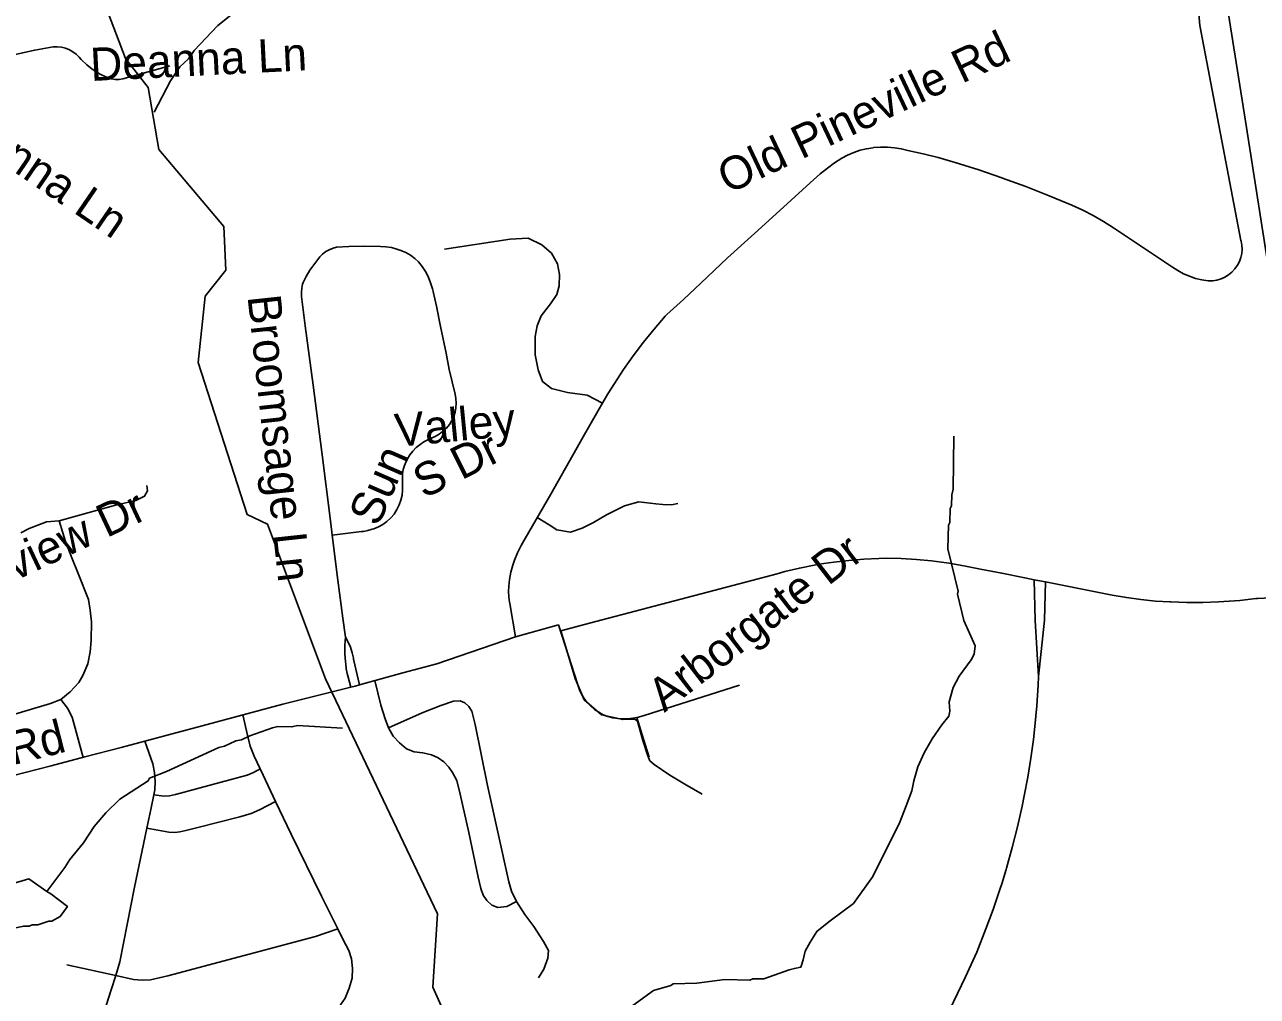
# Model space of a CAD drawing. Extents: x 1383679 to 1536984, y 460658 to 651027.
# Drawn here: x 1435276 to 1438807, y 509221 to 512005 of the extents above; entities that cross this region are included whole.
import ezdxf

# ---------------------------------------------------------------- set-up
doc = ezdxf.new("R2010")
doc.units = 0
for name, color, linetype in [('Exist Hydrographic Creek Single Shore', 7, 'Continuous'), ('Exist Hydrographic Misc Water Feature', 7, 'Continuous'), ('Exist Railroad Mainline', 7, 'Continuous'), ('Exist Road Non-System Type 51', 7, 'Continuous'), ('Exist Road Non-System Type 51 Label', 7, 'Continuous')]:
    doc.layers.add(name, color=color, linetype=linetype)

msp = doc.modelspace()

# ---------------------------------------------------------------- linework, layer by layer
at = {"layer": 'Exist Hydrographic Creek Single Shore'}
msp.add_lwpolyline([(1436493.4, 509139), (1436445.4, 509248.2), (1436458.4, 509458.1), (1436137.4, 510130.8), (1435971.4, 510574), (1435913.4, 510601.5), (1435772.4, 511037.6), (1435792.4, 511227.6), (1435852.4, 511301.8), (1435846.4, 511426.7), (1435659.5, 511647.1), (1435629.4, 511825), (1435564.4, 511908.3), (1435405.4, 512328.4), (1435437.4, 512695.4), (1435492.5, 512937.2), (1435523.4, 513268), (1435362.5, 513937.6), (1435309.4, 514240.7), (1435323.4, 514539.1), (1435285.5, 514707.3), (1435189.5, 514925.8)], dxfattribs=at)
at = {"layer": 'Exist Hydrographic Misc Water Feature'}
for points in [[(1435646.5, 511754.1), (1435693.3, 511844.4), (1435720.1, 511883.8), (1435744.6, 511907.2), (1435761.2, 511930.8), (1435828.7, 512003.1), (1435885.7, 512048)], [(1437924.4, 510065.2), (1437936, 510106.7), (1437952.8, 510138.4), (1437987.8, 510185.5), (1437996.1, 510201.4), (1437998.7, 510225.3), (1437966.3, 510298), (1437948.8, 510373.6), (1437950.1, 510382.3), (1437921, 510503.2), (1437922.1, 510570.9), (1437926.3, 510578.8), (1437927.2, 510618.7), (1437931.3, 510626.6), (1437932, 510658.6), (1437936.3, 510674.5), (1437937.7, 510826.4)], [(1437466.5, 509297.7), (1437481.1, 509301.4), (1437499.3, 509304.6), (1437505.7, 509325.9), (1437512.2, 509350.9), (1437525.8, 509376.9), (1437545.6, 509407.5), (1437579.7, 509435.4), (1437620.9, 509465.5), (1437650, 509487.6), (1437705.4, 509565.2), (1437743.9, 509642), (1437781.3, 509715.2), (1437801.4, 509767.3), (1437817.8, 509810), (1437823.3, 509838.5), (1437834.8, 509878.9), (1437852.4, 509919.1), (1437875.9, 509959.1), (1437903, 509999.2), (1437923.8, 510023.8), (1437926.2, 510038.9), (1437924.4, 510065.2)], [(1436185.8, 509989.7), (1436057.4, 509997), (1436041.3, 509993.4), (1436001.3, 509994.3), (1435985.2, 509990.7), (1435920.7, 509968.1), (1435896.4, 509956.7), (1435880.3, 509953), (1435848, 509937.8), (1435831.9, 509934.1), (1435682.4, 509865.5), (1435633.7, 509846.8), (1435629.8, 509838.7), (1435548.6, 509786.5), (1435507.8, 509747.5), (1435474.9, 509708.3), (1435443.8, 509661), (1435404.9, 509613.9), (1435390.3, 509590.2), (1435338.6, 509521.7)], [(1435338.6, 509521.7), (1435350.7, 509515.1), (1435398, 509479.1), (1435377.3, 509450.6), (1435353, 509437.1), (1435345, 509437.3), (1435312.8, 509426), (1435296.8, 509426.4), (1435288.7, 509422.6), (1435272.7, 509422.9), (1435240.5, 509415.7), (1435200.1, 509396.6), (1435184.1, 509396.9), (1435170.2, 509403.3), (1435159, 509437.5), (1435157.9, 509477.5), (1435162.2, 509493.4), (1435174.5, 509509.1), (1435233.2, 509541.8), (1435287.6, 509558.5), (1435338.6, 509521.7)], [(1436839.9, 508986.1), (1436882.6, 509030.9), (1436973.1, 509148.8), (1437005.8, 509180.1), (1437008, 509188), (1437077.1, 509238.4), (1437126.5, 509252.5), (1437133.5, 509257.2), (1437201.5, 509259.6), (1437281.8, 509269.8), (1437353.8, 509268.2), (1437361.9, 509272), (1437393.9, 509271.3), (1437466.5, 509297.7)]]:
    msp.add_lwpolyline(points, dxfattribs=at)
at = {"layer": 'Exist Railroad Mainline'}
msp.add_lwpolyline([(1438885.5, 511015.1), (1438773.4, 511728.4), (1438664.9, 512414.7)], dxfattribs=at)
at = {"layer": 'Exist Road Non-System Type 51'}
for p, q in [((1438168.1, 510415), (1438200.4, 510408.6)), ((1435396.2, 509311.8), (1435536.4, 509281.3))]:
    msp.add_line(p, q, dxfattribs=at)
for points in [[(1436681.7, 510251.1), (1436665.5, 510346.4), (1436664.7, 510350.4), (1436662.5, 510365.7), (1436661.8, 510380.9), (1436662.5, 510396.2), (1436664.9, 510415.6), (1436669, 510436.5), (1436674.5, 510457), (1436679.4, 510471.3), (1436687.9, 510492.3), (1436697.8, 510512.6), (1436709.3, 510532.7), (1436782.7, 510660.3), (1436845.8, 510771.6), (1436875.8, 510824), (1436918.2, 510897.8), (1436946.7, 510947.2), (1436965.3, 510977.3), (1436991.4, 511017.2), (1437019, 511056.3), (1437019.2, 511056.6), (1437048.5, 511095.4), (1437079, 511133.1), (1437110.8, 511170.1), (1437115.9, 511174.6), (1437163.3, 511217.9), (1437212.5, 511264.2), (1437289.5, 511337.1), (1437366.3, 511406.5), (1437449.7, 511481.9), (1437526, 511551.5), (1437554.8, 511577.6), (1437575.8, 511594.3), (1437596.1, 511609.7), (1437617.4, 511622.9), (1437633.5, 511631.4), (1437651, 511639), (1437669.1, 511645.1), (1437687.6, 511649.6), (1437706.4, 511652.7), (1437707.7, 511652.8), (1437727.6, 511654.3), (1437747.5, 511654.3), (1437767.4, 511652.7), (1437787.1, 511649.5), (1437806.5, 511644.8), (1437849.8, 511635.5), (1437892.6, 511624.7), (1437935.1, 511612.4), (1437941.2, 511610.5), (1438009.4, 511588.9), (1438075, 511566.4), (1438077, 511565.8), (1438144.2, 511541.2), (1438210.8, 511515.1), (1438276.2, 511487.8), (1438307.2, 511473.7), (1438337.5, 511458.2), (1438367.1, 511441.3), (1438395.8, 511423.1), (1438423.7, 511403.6), (1438564.7, 511310.5), (1438580.1, 511300.4), (1438596.3, 511291.6), (1438613.2, 511284.2), (1438630.7, 511278.2), (1438648.6, 511273.8), (1438666.8, 511271), (1438667.5, 511270.9), (1438679.7, 511271.4), (1438691.7, 511273.4), (1438703.4, 511277), (1438714.5, 511282.1), (1438724.9, 511288.6), (1438734.3, 511296.3), (1438742.7, 511305.2), (1438749.9, 511315.1), (1438750.3, 511315.8), (1438755.9, 511326.4), (1438760, 511337.6), (1438762.6, 511349.2), (1438763.6, 511361.1), (1438763.1, 511373), (1438760.9, 511384.7), (1438760.5, 511386.4), (1438643, 512002.4), (1438638.6, 512047.5)], [(1435691.9, 511886.9), (1435556.9, 511850.1), (1435546.2, 511848.4), (1435535.3, 511848.3), (1435524.5, 511849.7), (1435514.1, 511852.7), (1435509.7, 511854.4), (1435493.7, 511862), (1435478.4, 511871), (1435464, 511881.3), (1435453.7, 511889.9), (1435437.2, 511905.6), (1435432.1, 511911.8), (1435423.5, 511920.1), (1435414, 511927.2), (1435403.6, 511933), (1435392.5, 511937.3), (1435380.9, 511940.2), (1435369.1, 511941.5), (1435357.2, 511941.2), (1435304.2, 511932.4), (1435247.9, 511919.5)], [(1436156.9, 510542.2), (1436152.6, 510576.3), (1436127.3, 510780.6), (1436101.8, 510972.3), (1436079.3, 511142.4), (1436068.7, 511226.8), (1436068.3, 511238.6), (1436069.3, 511250.1), (1436071.8, 511261.7), (1436073.1, 511266), (1436082.2, 511283.8), (1436092.9, 511301.6), (1436098.5, 511309.8), (1436121.1, 511339.8), (1436129.2, 511348), (1436138.3, 511354.9), (1436148.3, 511360.5), (1436159, 511364.7), (1436169.2, 511367.3), (1436204.4, 511369.2), (1436249.4, 511370.3), (1436295.5, 511369.8), (1436310.8, 511368.9), (1436326.3, 511366.4), (1436338.9, 511363), (1436353.2, 511358.4), (1436367.4, 511352.2), (1436380.7, 511344.4), (1436393.1, 511335.3), (1436403.9, 511325.3), (1436414.7, 511311.9), (1436423.9, 511297.7), (1436431.3, 511283.2), (1436438.6, 511265.8), (1436444.4, 511247.9), (1436446.4, 511240.4), (1436455.3, 511198.7), (1436467, 511140.2), (1436483.1, 511063.9), (1436492.1, 511017.5), (1436508.7, 510946.7), (1436511.1, 510933.9), (1436511.9, 510920.8), (1436511.2, 510907.8), (1436508.8, 510895), (1436505, 510882.5), (1436504.9, 510882.1), (1436499.8, 510870.8), (1436492.8, 510859.6), (1436484.4, 510849.5), (1436475, 510840.8), (1436473, 510839.3), (1436463, 510831.7), (1436451.6, 510825.4), (1436444.8, 510822.5), (1436419.7, 510809.6), (1436408.3, 510802.1), (1436397.7, 510793.3), (1436388.1, 510783.5), (1436379.6, 510772.7), (1436372.1, 510760.9), (1436371.2, 510759.2), (1436365.8, 510747.3), (1436363.9, 510742.1), (1436360.4, 510730.6), (1436358.4, 510718.6), (1436357.9, 510706.6), (1436358.5, 510698.3), (1436358.4, 510671.7), (1436356.9, 510657.6), (1436353.6, 510643.1), (1436348.6, 510629.1), (1436342, 510615.7), (1436333.9, 510603.2), (1436324.4, 510591.8), (1436313.7, 510581.9), (1436302, 510573.5), (1436289.2, 510566.5), (1436276, 510561.1), (1436271.5, 510559.7), (1436259.1, 510555.8), (1436246.3, 510553.3), (1436240.9, 510552.8), (1436156.9, 510542.2)], [(1436478.6, 511362.4), (1436666.4, 511390.7), (1436717.8, 511393.6), (1436757.2, 511374.3), (1436784.6, 511350.8), (1436801.8, 511319.9), (1436808.1, 511289.1), (1436806.9, 511256.9), (1436800.5, 511232.5), (1436782.5, 511205.5), (1436755.5, 511170.8), (1436743.9, 511142.6), (1436738.4, 511112.2), (1436738.4, 511059.4), (1436747, 511016.6), (1436759, 510982.8), (1436785.5, 510963), (1436830.9, 510951.8), (1436887.5, 510943.3), (1436931.4, 510920.9)], [(1435374.5, 510584), (1435474, 510611.1), (1435535.6, 510628.1), (1435594.4, 510642.2), (1435619.1, 510654.1), (1435627.6, 510669.3), (1435625.4, 510685.2)], [(1436744, 510593.5), (1436778.2, 510572.5), (1436800.5, 510558), (1436839.9, 510551.2), (1436872.5, 510562.2), (1436905, 510578.5), (1436942.8, 510600.8), (1436961.6, 510610.2), (1436994.1, 510626.5), (1437035.2, 510638.5), (1437084.1, 510632.5), (1437103.8, 510630.8), (1437128.6, 510629.9), (1437146.6, 510633.4)], [(1435264.4, 510549.7), (1435288.6, 510561.8), (1435338, 510580.7), (1435374.5, 510584)], [(1435374.5, 510584), (1435384.6, 510548.9), (1435392.6, 510524.1), (1435410.6, 510477.5), (1435428.9, 510433.1), (1435458.1, 510358.1), (1435463.4, 510327.8), (1435466.9, 510294.1), (1435465.9, 510240.4), (1435463.2, 510208.2), (1435456.4, 510173.8), (1435442.6, 510140.9), (1435431.1, 510120.2), (1435405.6, 510093.5), (1435379.6, 510072.1)], [(1436194.5, 510250.5), (1436187.2, 510305.3), (1436173.1, 510413.8), (1436156.9, 510542.2)], [(1436811.7, 510268.2), (1436893.9, 510290.4), (1437060.8, 510334.4), (1437232.1, 510379.8), (1437431.2, 510432.1), (1437453.8, 510438.2), (1437495.5, 510448.2), (1437537.5, 510456.6), (1437551.4, 510459.1), (1437594, 510465.6), (1437636.7, 510470.5), (1437679.5, 510473.9), (1437722.5, 510475.8), (1437743.5, 510476.6), (1437787.1, 510475.7), (1437830.6, 510473.1), (1437874, 510468.9), (1437917.2, 510463.2), (1437924.7, 510462.1), (1437971, 510454.2), (1438013.8, 510445.4), (1438075, 510433.3), (1438140.8, 510420.3), (1438168.1, 510415)], [(1438180.7, 510137.6), (1438170.6, 510297.9), (1438168.1, 510415)], [(1438180.7, 510137.6), (1438197.8, 510299.5), (1438200.4, 510408.6)], [(1438200.4, 510408.6), (1438257.9, 510397.4), (1438391.3, 510370.8), (1438432.4, 510363.6), (1438473.8, 510357.9), (1438515.4, 510353.9), (1438557.1, 510351.4), (1438559.4, 510351.3), (1438605.1, 510349.8), (1438650.9, 510349.8), (1438696.6, 510351.5), (1438711.8, 510352.4), (1438757.7, 510355.9), (1438803.4, 510360.9), (1438808.8, 510361.6), (1438845.1, 510363.5), (1438881.4, 510363.9), (1438947.7, 510372.8), (1439049.3, 510374.8)], [(1437029.8, 510020.5), (1437018.4, 510018.2), (1437002.1, 510016.5), (1436985.8, 510016.4), (1436975.1, 510017), (1436960.8, 510019.3), (1436946.9, 510023.1), (1436933.4, 510028.4), (1436920.6, 510035.1), (1436908.6, 510043.2), (1436897.6, 510052.5), (1436887.6, 510063), (1436878.8, 510074.5), (1436871.4, 510086.9), (1436865.3, 510100), (1436860.7, 510113.7), (1436804.7, 510285.6), (1436681.7, 510251.1)], [(1436811.8, 510268.2), (1436831.4, 510202.2), (1436852.8, 510131.9), (1436878.5, 510071.1), (1436928.1, 510028.2), (1436989, 510014.5), (1437023.6, 510015.6), (1437028.1, 510012.9), (1437031.4, 510009.6), (1437047.2, 509954.6), (1437061.1, 509910.7), (1437067.1, 509896.6), (1437078.8, 509885.8), (1437124.4, 509855.2), (1437166.8, 509829), (1437217.1, 509800.3)], [(1436194.5, 510250.5), (1436192.9, 510227.1), (1436192.9, 510203.6), (1436194.5, 510180.2), (1436195.3, 510173.6), (1436196.5, 510160), (1436199.4, 510146.7), (1436201.7, 510139.4), (1436210.1, 510107.4)], [(1436194.5, 510250.5), (1436202.4, 510236.3), (1436208.9, 510221.3), (1436214, 510205.8), (1436217.5, 510189.9), (1436217.9, 510187.3), (1436235.3, 510114)], [(1436681.7, 510251.1), (1436456.6, 510174.3), (1436359.5, 510148.3), (1436235.3, 510114)], [(1436279, 510126), (1436295.9, 510055.9), (1436308.5, 510016.1), (1436317.9, 509990.7)], [(1437727.1, 508761.5), (1437740.5, 508790), (1437871.1, 509066), (1437937.2, 509205.8), (1437971.7, 509277.4), (1437997.8, 509335.8), (1438003.4, 509348.5), (1438029.6, 509414.4), (1438050.4, 509470.6), (1438069.8, 509527.3), (1438075, 509544.1), (1438087.6, 509584.6), (1438089, 509589.1), (1438105.3, 509647.8), (1438120.1, 509706.7), (1438133.4, 509766.1), (1438139.5, 509795.6), (1438150, 509849.5), (1438158.9, 509903.4), (1438166.3, 509957.5), (1438170.2, 509994.3), (1438175.7, 510053.7), (1438179.5, 510113.2), (1438180.7, 510137.6)], [(1436210.1, 510107.4), (1436019.1, 510059.6), (1436014.9, 510058.5), (1435784.2, 509996.4), (1435673.3, 509966.5), (1435551.9, 509934.1), (1435448.4, 509907.2), (1435351.6, 509882.1), (1435239.5, 509853.2), (1435077.6, 509810.4), (1434953.3, 509776.9), (1434824.8, 509743.7), (1434712.5, 509716.2), (1434548.1, 509673.7), (1434430.2, 509646.4)], [(1436235.3, 510114), (1436222.2, 510110.4), (1436210.1, 510107.4)], [(1437029.8, 510020.5), (1437034.5, 510021.4), (1437050.1, 510026.2), (1437323.5, 510113.1)], [(1435379.6, 510072.1), (1435349.6, 510060.8), (1435201.5, 510016.4), (1435182.4, 510011.8), (1435100.4, 509991.7), (1435077, 509985.9), (1435011.2, 509966.8), (1434924.2, 509975.7)], [(1435379.6, 510072.1), (1435398.4, 510046.6), (1435411.4, 510021.5), (1435443.4, 509905.9)], [(1436317.9, 509990.7), (1436414.2, 510034), (1436467.9, 510055.1), (1436504.4, 510066.9), (1436523, 510067.8), (1436536.5, 510062.7), (1436548.4, 510051.7), (1436556.9, 510038.9), (1436566.1, 510000), (1436601.9, 509825.3), (1436662.9, 509549.1), (1436670.4, 509522.8), (1436684.9, 509493.2)], [(1435900.6, 510027.8), (1435913.6, 509969.5), (1435921.4, 509938.2), (1435932.8, 509909.5), (1435950.1, 509873)], [(1437064.6, 509906.6), (1437048.3, 509958.6), (1437029.8, 510020.5)], [(1436317.9, 509990.7), (1436331.4, 509966.9), (1436349.2, 509947.4), (1436369.6, 509930.5), (1436391.6, 509922), (1436416.1, 509919.4), (1436440.8, 509913.5), (1436460.2, 509905.1), (1436476.4, 509893.2), (1436490.8, 509877.9), (1436501.8, 509862.7), (1436513.6, 509839.8), (1436523, 509800.8), (1436548.4, 509690.6), (1436574.6, 509562.7), (1436582.4, 509530.4), (1436589.1, 509510.9), (1436600.1, 509495.7), (1436614.5, 509482.9), (1436631.4, 509476.2), (1436656.9, 509478.8), (1436684.9, 509493.2)], [(1435620.1, 509952.3), (1435642.4, 509887.3), (1435647.9, 509862.7), (1435649.4, 509837.2), (1435648.6, 509812.6), (1435645.8, 509799)], [(1435645.8, 509799), (1435674.9, 509794.6), (1435690.4, 509796.2), (1435708.1, 509799.9), (1435838.4, 509835.4), (1435912.6, 509855.3), (1435931, 509862.9), (1435950.1, 509873)], [(1435950.1, 509873), (1435958.9, 509854.8), (1435994.6, 509779.2)], [(1435645.8, 509799), (1435637, 509757.1), (1435625.6, 509703.2)], [(1435625.6, 509703.2), (1435688.9, 509691.8), (1435705.5, 509691.2), (1435720.6, 509692.8), (1435737.8, 509696.6), (1435771.6, 509704.7), (1435892.2, 509735.9), (1435924.5, 509745.1), (1435948.8, 509755.8), (1435994.6, 509779.2)], [(1435994.6, 509779.2), (1436038.8, 509686.1), (1436125.8, 509508.8), (1436172.9, 509414.4)], [(1435625.6, 509703.2), (1435590, 509534.3), (1435548.4, 509320.8), (1435536.4, 509281.3)], [(1436684.9, 509493.2), (1436708.6, 509455.8), (1436734, 509421.1), (1436762, 509378.7), (1436776.4, 509352.4), (1436774.6, 509330.4), (1436762.9, 509299), (1436747.6, 509274.4)], [(1436172.9, 509414.4), (1436187.4, 509385.3), (1436203.9, 509353.2), (1436211.8, 509328.8), (1436215.2, 509301), (1436213.5, 509273.2), (1436204.9, 509244.5), (1436193.5, 509216.7), (1436180.5, 509196.7), (1436164.9, 509181.9), (1436149.1, 509170.6), (1436129.1, 509158.4), (1436097, 509148), (1435640.6, 509030.7), (1435514.2, 508997.6)], [(1435536.4, 509281.3), (1435587.6, 509270.1), (1435612.6, 509267.6), (1435636.1, 509269.2), (1435685.4, 509280.1), (1436109.1, 509392.9), (1436172.9, 509414.4)], [(1435536.4, 509281.3), (1435522.9, 509237.6), (1435503.6, 509177.5), (1435496.8, 509147.4), (1435492.9, 509120.4), (1435493.6, 509095.8), (1435497.5, 509064.2), (1435514.2, 508997.6)]]:
    msp.add_lwpolyline(points, dxfattribs=at)

# ---------------------------------------------------------------- texts
at = {"layer": 'Exist Road Non-System Type 51 Label'}
for s, rotation, p in [('Deanna Ln', 2.8633, (1435465.7, 511843.5)), ('Old Pineville Rd', 25.2881, (1437290.5, 511518.8)), ('Deanna Ln', 325.6469, (1435015.5, 511739.7)), ('Broomsage Ln', 276.1699, (1435913.9, 511226.7)), ('Valley', 5.5782, (1436340.9, 510795)), ('S Dr', 26.3762, (1436419.4, 510646.2)), ('Sun', 66.3795, (1436288.2, 510564)), ('Branchview Dr', 25.1757, (1434884, 510239.7)), ('Arborgate Dr', 37.6976, (1437108.6, 510033.3)), ('E Arrowood Rd', 14.3407, (1434564.3, 509710.1))]:
    msp.add_text(s, height=95, rotation=rotation, dxfattribs=at).set_placement(p)

doc.saveas('drawing.dxf')
